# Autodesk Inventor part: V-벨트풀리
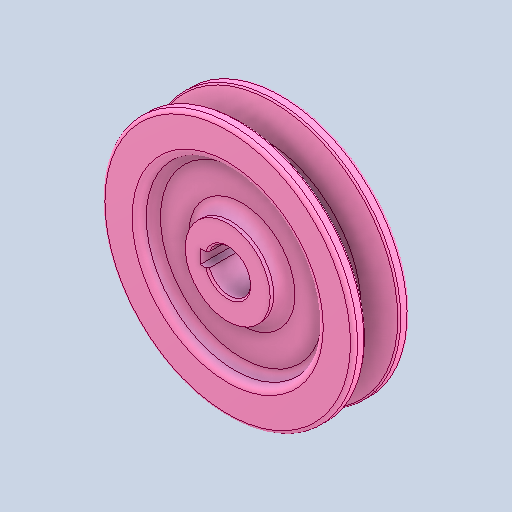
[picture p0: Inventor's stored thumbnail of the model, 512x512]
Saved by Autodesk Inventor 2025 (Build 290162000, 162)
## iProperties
Created: 2024-08
Part Number: V-벨트풀리
Material: 강철, 연강
Document SubType Name: Modeling
Designer: 학생
Density: 7.86 g/cm^3
Appearance: 기본값
Author: jhkim
Sending System: Autodesk Inventor 2025
Preprocessor: ST-DEVELOPER v20
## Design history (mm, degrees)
feature "Solid1"
node "솔리드1"
